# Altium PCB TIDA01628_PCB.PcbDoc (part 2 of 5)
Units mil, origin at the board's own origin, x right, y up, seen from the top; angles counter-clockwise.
Board outline 14212.6 x 5944.88 mil, 4 copper layers (Top Layer, GND, 5V, Bottom Layer), stack 60.8 mil thick; 304 components, 201 nets, 839 pads, 2143 vias.
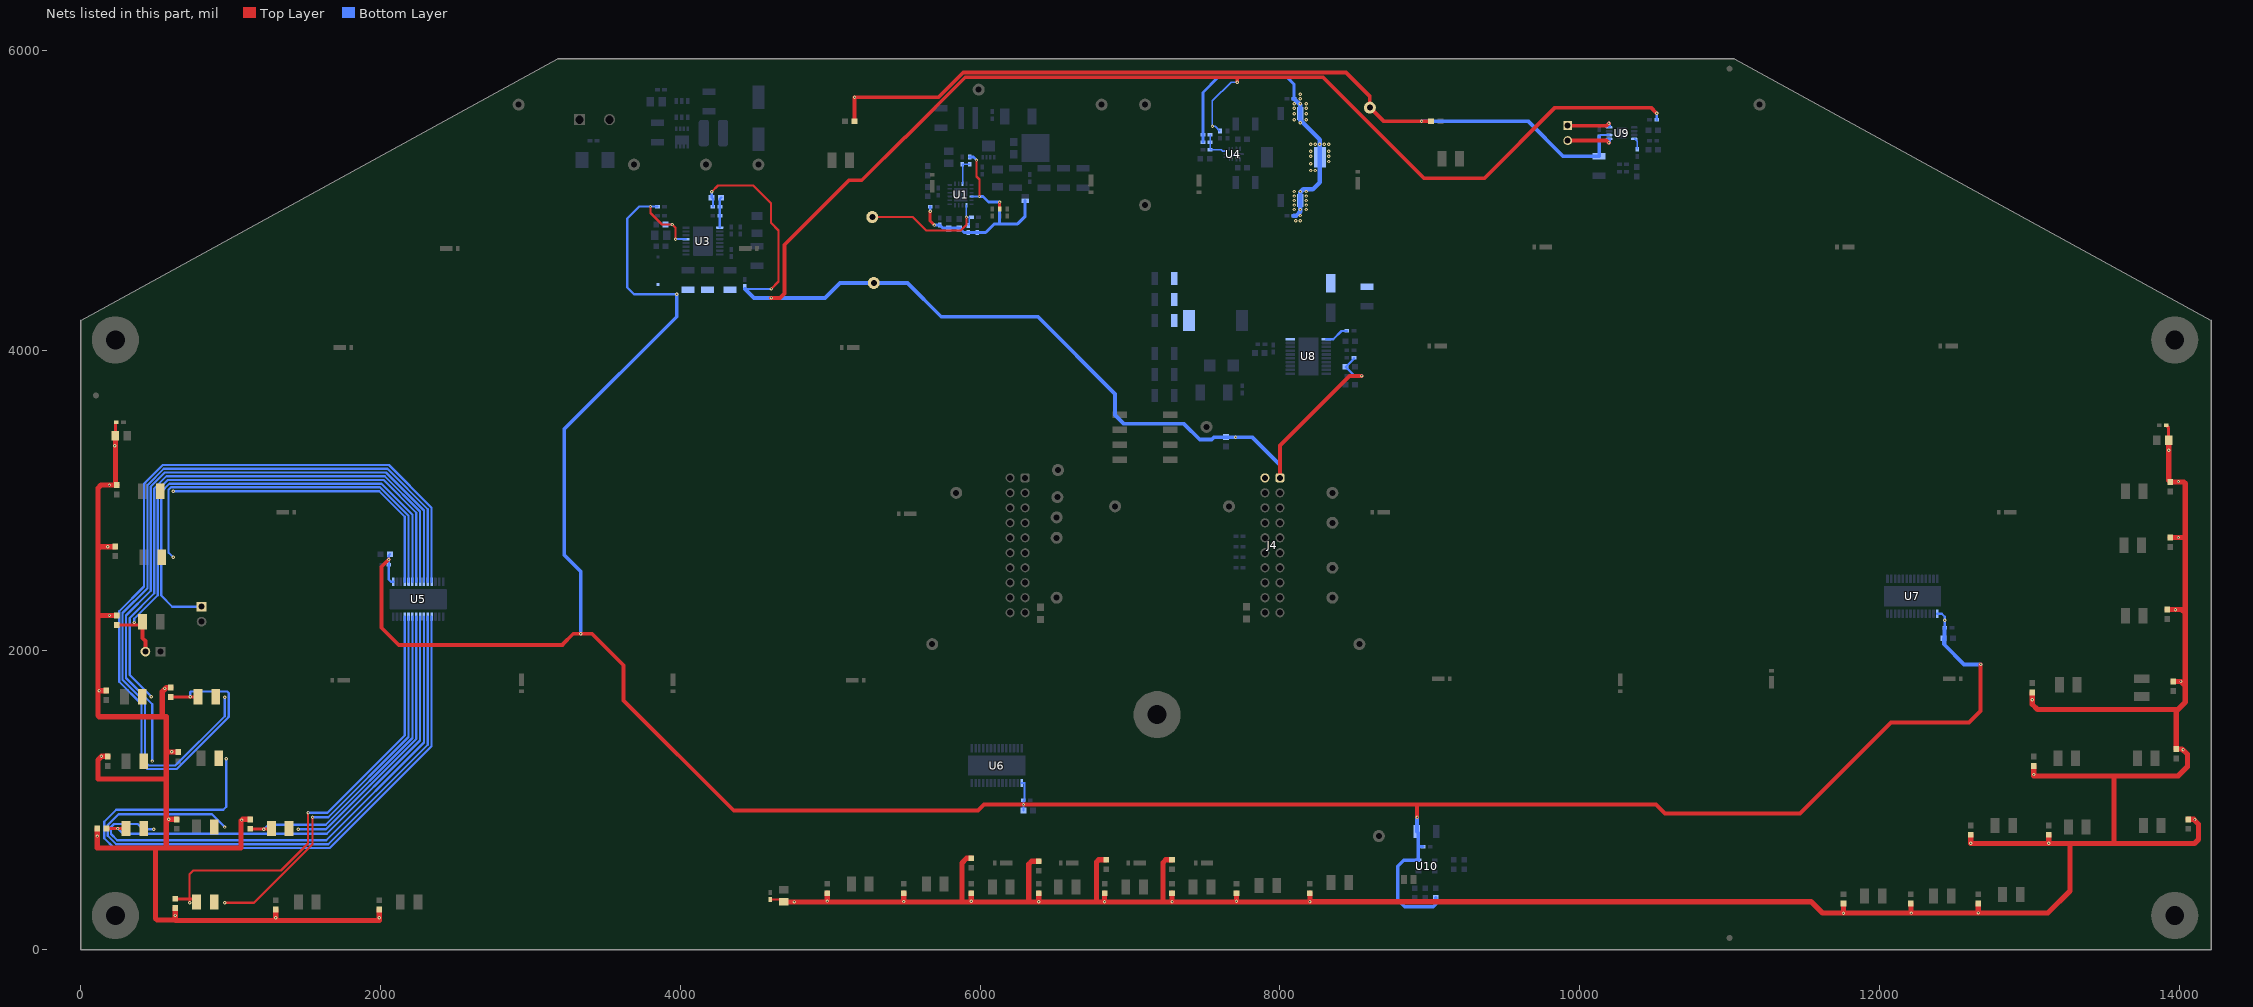
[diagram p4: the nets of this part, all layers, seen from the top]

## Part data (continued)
C16 C33 C43 C45 C47: library part CMP-0008019-2, "CAP, CERM, 4.7 uF, 16 V, +/- 10%, X7R, AEC-Q200 Grade 1, 0805", Cap_Case=0805, Manufacturer=MuRata, Supplier Part Number 1=GCM21BR71C475KA73K-ND, TempCo=X7R, Tolerance_%=10%, Value1=Unknown, Value2=16V, ValueDisplayed=4.7uF
C17 C34 C40 C49 C51 C53 C65 C66 C74: library part CMP-0007136-5, "CAP, CERM, 1 uF, 16 V, +/- 10%, X7R, AEC-Q200 Grade 1, 0603", Cap_Case=0603, Manufacturer=MuRata, Supplier Part Number 1=490-5241-6-ND, TempCo=X7R, Tolerance_%=10%, Value1=Unknown, Value2=16V, ValueDisplayed=1uF
C18: library part CMP-0006310-2, "CAP, CERM, 150 pF, 50 V, +/- 5%, C0G/NP0, AEC-Q200 Grade 1, 0402", Cap_Case=0402, Manufacturer=TDK, Supplier Part Number 1=445-5598-1-ND, TempCo=C0G/NP0, Tolerance_%=5%, Value1=Unknown, Value2=50V, ValueDisplayed=150pF
C19: library part CMP-0006321-2, "CAP, CERM, 4700 pF, 50 V, +/- 10%, X7R, AEC-Q200 Grade 1, 0402", Cap_Case=0402, Manufacturer=TDK, Supplier Part Number 1=445-5607-1-ND, TempCo=X7R, Tolerance_%=10%, Value1="0.413508 ohm", Value2=50V, ValueDisplayed=4700pF
C22 C27 C30 C32 C73: library part CMP-0007094-5, "CAP, CERM, 0.22 uF, 50 V, +/- 10%, X7R, AEC-Q200 Grade 1, 0603", Cap_Case=0603, Manufacturer=TDK, Supplier Part Number 1=445-6926-1-ND, TempCo=X7R, Tolerance_%=10%, Value1="0.021699 ohm", Value2=50V, ValueDisplayed=0.22uF
C23 C24 C25 C35 C36: library part CMP-0009154-2, "CAP, CERM, 22 uF, 16 V, +/- 20%, X7R, AEC-Q200 Grade 1, 1210", Cap_Case=1210_280, Manufacturer=TDK, Supplier Part Number 1=445-5723-1-ND, TempCo=X7R, Tolerance_%=20%, Value1="0.002582 ohm", Value2=16V, ValueDisplayed=22uF
C26 C39: library part CMP-0006324-2, "CAP, CERM, 0.01 uF, 50 V, +/- 10%, X7R, AEC-Q200 Grade 1, 0402", Cap_Case=0402, Manufacturer=TDK, Supplier Part Number 1=445-6893-1-ND, TempCo=X7R, Tolerance_%=10%, Value1="0.333065 ohm", Value2=50V, ValueDisplayed=0.01uF
C41: library part CMP-0006327-2, "CAP, CERM, 0.015 uF, 50 V, +/- 10%, X7R, AEC-Q200 Grade 1, 0402", Cap_Case=0402, Manufacturer=TDK, Supplier Part Number 1=445-6894-1-ND, TempCo=X7R, Tolerance_%=10%, Value1="0.2162 ohm", Value2=50V, ValueDisplayed=0.015uF
C61: library part CMP-0006791-4, "CAP, CERM, 4.7 pF, 50 V, +/- 5%, C0G/NP0, 0603", Cap_Case=0603, Manufacturer=AVX, Supplier Part Number 1=478-1159-1-ND, TempCo=C0G/NP0, Tolerance_%=5%, Value1="0.633 ohm", Value2=50V, ValueDisplayed=4.7pF
C63: library part CMP-0010728-1, "CAP, AL, 33 uF, 35 V, +/- 20%, 0.36 ohm, AEC-Q200 Grade 2, SMD", Cap_Case=D, Manufacturer=Panasonic, Supplier Part Number 1=PCE3840CT-ND, Tolerance_%=20%, Value1="0.36 ohm", Value2=35V, ValueDisplayed=33uF
C67: library part CMP-0006989-4, "CAP, CERM, 100 pF, 50 V, +/- 5%, C0G/NP0, 0603", Cap_Case=0603, Manufacturer=TDK, Supplier Part Number 1=445-173611-1-ND, TempCo=C0G/NP0, Tolerance_%=5%, Value1=Unknown, Value2=50V, ValueDisplayed=100pF
C70 C72: library part CMP-0007138-4, "CAP, CERM, 0.47 uF, 16 V, +/- 10%, X7R, AEC-Q200 Grade 1, 0603", Cap_Case=0603, Manufacturer=MuRata, Supplier Part Number 1=490-4775-1-ND, TempCo=X7R, Tolerance_%=10%, Value1=Unknown, Value2=16V, ValueDisplayed=0.47uF
C71: library part CMP-0006352-2, "CAP, CERM, 0.01 uF, 25 V, +/- 10%, X7R, 0402", Cap_Case=0402, Manufacturer=MuRata, Supplier Part Number 1=490-6043-2-ND, TempCo=X7R, Tolerance_%=10%, Value1=Unknown, Value2=25V, ValueDisplayed=0.01uF
D1: library part CMP-0028903-1, "Diode, Schottky, 60 V, 10 A, AEC-Q101, TO-277A", Manufacturer=Vishay-Semiconductor, Supplier Part Number 1=V10P6-M3/87A-ND, Value1=10A, Value2=0.59V
D2: library part CMP-0005564-2, "Diode, TVS, Bi, 33 V, SMB", Manufacturer="Diodes Inc.", Power_W=5W, Supplier Part Number 1=SMBJ33CA-FDICT-ND
D3 D4 D5 D6 D43 D44 D45 D46 D47 D48 D49 D50 D52 D53 D54 D55 D56 D57 D58 D59 D60 D61 D62 D63 D64 D65 D66 D67: "LED, White, SMD", Color=White, Manufacturer=OSRAM, Supplier Part Number 1="KW DPLS32.EC-6H6J-4F8G-1-ND", Value1=W, Value2=3.15V
D7 D8 D9 D25 D26 D27: library part CMP-0003010-2, "LED, Super Red, SMD", Color="Super Red", Manufacturer=OSRAM, Supplier Part Number 1=475-2516-1-ND, Value1=W, Value2=1.8V
D10 D11 D12 D13 D28 D29 D30 D31: library part CMP-0003012-2, "LED, Yellow, SMD", Color=Yellow, Manufacturer=OSRAM, Supplier Part Number 1=475-2562-1-ND, Value1=W, Value2=1.8V
D14: library part CMP-0003013-2, "LED, Blue, SMD", Color=Blue, Manufacturer=OSRAM, Supplier Part Number 1="LB T673-L2P1-25-Z-ND", Value1=W, Value2=3.1V
D15 D16 D17 D18 D19 D20 D21 D22 D23 D24 D32 D33 D34 D35 D36 D37 D38 D39 D40 D41 D42: library part CMP-0003009-2, "LED, Green, SMD", Color=Green, Manufacturer=OSRAM, Supplier Part Number 1="LG T67K-G2K1-24-Z-ND", Value1=W, Value2=1.8V
D51: library part CMP-0028810-1, "Diode, Schottky, 60 V, 3 A, AEC-Q101, SMA", Manufacturer="Fairchild Semiconductor", Supplier Part Number 1=SSA36CT-ND, Value1=3A, Value2=0.75V
D68 D69: "LED, Red, SMD", Color=red, Manufacturer=Lite-On, Supplier Part Number 1=160-1415-1-ND, Value1=W, Value2=2V
FID1 FID2 FID3: library part CMP-0077181-1, "Fiducial mark.  There is nothing to buy or mount.", Manufacturer=N/A
H1 H2 H3 H4 H5: library part CMP-0003617-1, "Machine Screw, Round, #4-40 x 1/4, Nylon, Philips panhead", Manufacturer="B&F Fastener Supply", Supplier Part Number 1=H542-ND
H6 H7 H8 H9 H10: library part CMP-0003610-1, "Standoff, Hex, 0.5\"L #4-40 Nylon", Manufacturer=Keystone, Supplier Part Number 1=36-1902C-ND
J1: library part CMP-0055551-1, "Header (Shrouded), 5.08mm, 2x1, Tin, R/A, TH", Color=Green, Current_A=12A, Manufacturer="Phoenix Contact", Supplier Part Number 1=277-1095-ND, Voltage_V=400V
J2 J3: library part CMP-0054566-1, "Header, 100mil, 2x1, Gold, TH", Color=Black, Current_A=3A, Manufacturer="Sullins Connector Solutions", Supplier Part Number 1=S1011E-02-ND, Voltage_V=1.8kV
J4 J5: library part CMP-0054623-1, "Header, 2.54mm, 10x2, Tin, TH", Color=Black, Current_A=3A, Manufacturer="Sullins Connector Solutions", Supplier Part Number 1=S2012E-10-ND
J6: library part CMP-0054947-1, "Header, 100mil, 2x1, Gold, TH", Manufacturer="TE Connectivity"
L1: library part CMP-0061081-1, "Inductor, Shielded, Composite, 560 nH, 11.3 A, 0.008 ohm, AEC-Q200 Grade 1, SMD", Manufacturer=Coilcraft, Value1="0.008 ohm", Value2=11.3A, ValueDisplayed=560nH
L2: library part CMP-0064228-1, "Inductor, Shielded Drum Core, Ferrite, 1 uH, 4 A, 0.049 ohm, SMD", Manufacturer="Wurth Elektronik", Supplier Part Number 1=732-1249-1-ND, Value1="0.049 ohm", Value2=4A, ValueDisplayed=1uH
L3: library part CMP-0063808-1, "Inductor, Shielded Drum Core, Ferrite, 1.8 uH, 2.45 A, 0.02 ohm, SMD", Manufacturer="Wurth Elektronik", Supplier Part Number 1=732-1094-1-ND, Value1="0.02 ohm", Value2=2.45A, ValueDisplayed=1.8uH
L4: library part CMP-0064214-1, "Inductor, Shielded Drum Core, Ferrite, 1.5 uH, 6.2 A, 0.0137 ohm, SMD", Manufacturer="Wurth Elektronik", Supplier Part Number 1=732-2972-1-ND, Value1="0.0137 ohm", Value2=6.2A, ValueDisplayed=1.5uH
L5: library part CMP-0064217-1, "Inductor, Shielded Drum Core, Ferrite, 4.7 uH, 4 A, 0.026 ohm, SMD", Manufacturer="Wurth Elektronik", Supplier Part Number 1=732-2975-1-ND, Value1="0.026 ohm", Value2=4A, ValueDisplayed=4.7uH
LBL1: library part CMP-0003625-1, "Thermal Transfer Printable Labels, 0.650\" W x 0.200\" H - 10,000 per roll", Manufacturer=Brady, Supplier Part Number 1=97C5133
Logo1: library part CMP-0074840-1, "ESD Susceptible Symbol"
Logo2: library part CMP-0074839-1
Logo3: library part CMP-0074847-1, "FCC_disclaimer"
NTG1: "Single point connection between nets."
Q1: library part CMP-0067553-1, "MOSFET, N-CH, 60 V, 15 A, AEC-Q101, 8-PowerVDFN", Alternate Manufacturer=None, Manufacturer="Diodes Inc.", Supplier Part Number 1=DMT6007LFG-13-ND, Value1="0.0085 ohm", Value2="41.3 nC"
Q2: library part CMP-0000806-1, "MOSFET, N-CH, 60 V, 12.8 A, AEC-Q101, 3.4x0.9x2.7mm", Alternate Manufacturer=None, Manufacturer="NXP Semiconductor", Supplier Part Number 1=568-13030-1-ND, Value2="4.4 nC"
Q3: library part CMP-0002104-2, "Ambient Light Sensor in 0805 Package", Manufacturer=Vishay-Semiconductor, Supplier Part Number 1=751-1056-1-ND
R1 R64: library part CMP-0016110-3, "RES, 2.0, 5%, 0.75 W, AEC-Q200 Grade 0, 2010", Manufacturer=Vishay-Dale, PartNumber=CRCW20102R00JNEF, Power_W=750mW, Supplier Part Number 1=541-2.0WCT-ND, TempCo="200 ppm/C", Tolerance_%=5%, Value2=0.75W, Value_Code=2R00, ValueDisplayed=2.0
R2 R5 R6 R8 R10 R15 R18 R67: library part CMP-0026822-3, "RES, 0, 5%, 0.063 W, AEC-Q200 Grade 0, 0402", Manufacturer=Vishay-Dale, Power_W=63mW, Supplier Part Number 1=541-0.0JCT-ND, TempCo="200 ppm/C", Tolerance_%=5%, Value2=0.063W, Value_Code=0000, ValueDisplayed=0
R3: library part CMP-0026404-2, "RES, 49.9, 1%, 0.063 W, AEC-Q200 Grade 0, 0402", Manufacturer=Vishay-Dale, Power_W=63mW, Supplier Part Number 1=541-49.9LCT-ND, TempCo="100 ppm/C", Tolerance_%=1%, Value2=0.063W, Value_Code=49R9, ValueDisplayed=49.9
R4: library part CMP-0018571-2, "RES, 0.015, 1%, 1 W, 1206", Manufacturer=Vishay-Dale, Power_W=1W, Supplier Part Number 1=WSLP-.015CT-ND, TempCo="75 ppm/C", Tolerance_%=1%, Value_Code=R015, ValueDisplayed=0.015
R7: library part CMP-0023011-2, "RES, 2.00, 1%, 0.1 W, 0603", Manufacturer="Yageo America", Power_W=100mW, Supplier Part Number 1=311-2.00HRCT-ND, TempCo="200 ppm/C", Tolerance_%=1%, Value2=0.1W, Value_Code=2R00, ValueDisplayed=2.00
R9: library part CMP-0025963-3, "RES, 10.0, 1%, 0.063 W, AEC-Q200 Grade 0, 0402", Manufacturer=Vishay-Dale, Power_W=63mW, Supplier Part Number 1=541-10.0LCT-ND, TempCo="100 ppm/C", Tolerance_%=1%, Value2=0.063W, Value_Code=10R0, ValueDisplayed=10.0
R11 R12: library part CMP-0022667-4, "RES, 9.53 k, 1%, 0.1 W, AEC-Q200 Grade 0, 0603", Manufacturer=Vishay-Dale, Power_W=100mW, Supplier Part Number 1=541-9.53KHCT-ND, TempCo="100 ppm/C", Tolerance_%=1%, Value2=0.1W, Value_Code=9k53, ValueDisplayed=9.53k
R13: library part CMP-0026405-2, "RES, 4.02 k, 1%, 0.063 W, AEC-Q200 Grade 0, 0402", Manufacturer=Vishay-Dale, Power_W=63mW, Supplier Part Number 1=541-4.02KLCT-ND, TempCo="100 ppm/C", Tolerance_%=1%, Value2=0.063W, Value_Code=4k02, ValueDisplayed=4.02k
R14: library part CMP-0018573-3, "RES, 0, 5%, 0.25 W, AEC-Q200 Grade 0, 1206", Manufacturer=Vishay-Dale, Power_W=250mW, Supplier Part Number 1=541-0.0ECT-ND, TempCo="200 ppm/C", Tolerance_%=5%, Value2=0.25W, Value_Code=0000, ValueDisplayed=0
R16 R20: library part CMP-0025950-3, "RES, 100 k, 1%, 0.063 W, AEC-Q200 Grade 0, 0402", Manufacturer=Vishay-Dale, Power_W=63mW, Supplier Part Number 1=541-100KLCT-ND, TempCo="100 ppm/C", Tolerance_%=1%, Value2=0.063W, Value_Code=100k
R17: library part CMP-0026058-3, "RES, 18.0 k, 1%, 0.063 W, AEC-Q200 Grade 0, 0402", Manufacturer=Vishay-Dale, Power_W=63mW, Supplier Part Number 1=541-18.0KLCT-ND, TempCo="100 ppm/C", Tolerance_%=1%, Value2=0.063W, Value_Code=18k0, ValueDisplayed=18.0k
R19: library part CMP-0026379-2, "RES, 43.2 k, 1%, 0.063 W, AEC-Q200 Grade 0, 0402", Manufacturer=Vishay-Dale, Power_W=63mW, Supplier Part Number 1=541-43.2KLCT-ND, TempCo="100 ppm/C", Tolerance_%=1%, Value2=0.063W, Value_Code=43k2, ValueDisplayed=43.2k
R21 R22: library part CMP-0025975-3, "RES, 11.0 k, 1%, 0.063 W, AEC-Q200 Grade 0, 0402", Manufacturer=Vishay-Dale, Power_W=63mW, Supplier Part Number 1=541-11.0KLCT-ND, TempCo="100 ppm/C", Tolerance_%=1%, Value2=0.063W, Value_Code=11k0, ValueDisplayed=11.0k
R23: library part CMP-0026196-2, "RES, 24.9 k, 1%, 0.063 W, AEC-Q200 Grade 0, 0402", Manufacturer=Vishay-Dale, Power_W=63mW, Supplier Part Number 1=541-24.9KLCT-ND, TempCo="100 ppm/C", Tolerance_%=1%, Value2=0.063W, Value_Code=24k9, ValueDisplayed=24.9k
R24 R25 R26 R27: library part CMP-0025843-4, "RES, 68, 5%, 0.1 W, AEC-Q200 Grade 0, 0603", Manufacturer=Vishay-Dale, Power_W=100mW, Supplier Part Number 1=541-68GCT-ND, TempCo="200 ppm/C", Tolerance_%=5%, Value2=0.1W, Value_Code=68R0, ValueDisplayed=68
R28 R29 R30 R31 R32 R33 R34 R35 R36 R37 R38 R39 R40 R41 R43 R44 R45 R46 R47 R48 R49 R50 R51 R52 R53 R54 R55 R56 R57 R58 R59 R60 R61 R62 R63: library part CMP-0022037-5, "RES, 130, 1%, 0.1 W, AEC-Q200 Grade 0, 0603", Manufacturer=Vishay-Dale, Power_W=100mW, Supplier Part Number 1=541-130HCT-ND, TempCo="100 ppm/C", Tolerance_%=1%, Value2=0.1W, Value_Code=130R, ValueDisplayed=130
R42: library part CMP-0025854-4, "RES, 75, 5%, 0.1 W, AEC-Q200 Grade 0, 0603", Manufacturer=Vishay-Dale, Power_W=100mW, Supplier Part Number 1=541-75GCT-ND, TempCo="200 ppm/C", Tolerance_%=5%, Value2=0.1W, Value_Code=75R0, ValueDisplayed=75
R65: library part CMP-0026504-2, "RES, 681 k, 1%, 0.063 W, AEC-Q200 Grade 0, 0402", Manufacturer=Vishay-Dale, Power_W=63mW, Supplier Part Number 1=541-681KLCT-ND, TempCo="100 ppm/C", Tolerance_%=1%, Value2=0.063W, Value_Code=681k
R66: library part CMP-0025997-3, "RES, 130 k, 1%, 0.063 W, AEC-Q200 Grade 0, 0402", Manufacturer=Vishay-Dale, Power_W=63mW, Supplier Part Number 1=541-130KLCT-ND, TempCo="100 ppm/C", Tolerance_%=1%, Value2=0.063W, Value_Code=130k
R68: library part CMP-0026883-3, "RES, 24 k, 5%, 0.063 W, AEC-Q200 Grade 0, 0402", Manufacturer=Vishay-Dale, Power_W=63mW, Supplier Part Number 1=541-24KJCT-ND, TempCo="200 ppm/C", Tolerance_%=5%, Value2=0.063W, Value_Code=24k0, ValueDisplayed=24k
R69: library part CMP-0022324-4, "RES, 30.1 k, 1%, 0.1 W, AEC-Q200 Grade 0, 0603", Manufacturer=Vishay-Dale, Power_W=100mW, Supplier Part Number 1=541-30.1KHCT-ND, TempCo="100 ppm/C", Tolerance_%=1%, Value2=0.1W, Value_Code=30k1, ValueDisplayed=30.1k
R70 R72 R79 R80 R81 R82: library part CMP-0026945-3, "RES, 51 k, 5%, 0.063 W, AEC-Q200 Grade 0, 0402", Manufacturer=Vishay-Dale, Power_W=63mW, Supplier Part Number 1=541-51KJCT-ND, TempCo="200 ppm/C", Tolerance_%=5%, Value2=0.063W, Value_Code=51k0, ValueDisplayed=51k
R71: library part CMP-0022125-4, "RES, 1.47 k, 1%, 0.1 W, AEC-Q200 Grade 0, 0603", Manufacturer=Vishay-Dale, Power_W=100mW, Supplier Part Number 1=541-1.47KHCT-ND, TempCo="100 ppm/C", Tolerance_%=1%, Value2=0.1W, Value_Code=1k47, ValueDisplayed=1.47k
R73 R75: library part CMP-0025992-3, "RES, 12.4 k, 1%, 0.063 W, AEC-Q200 Grade 0, 0402", Manufacturer=Vishay-Dale, Power_W=63mW, Supplier Part Number 1=541-12.4KLCT-ND, TempCo="100 ppm/C", Tolerance_%=1%, Value2=0.063W, Value_Code=12k4, ValueDisplayed=12.4k
R74: library part CMP-0026090-3, "RES, 1.58 k, 1%, 0.063 W, AEC-Q200 Grade 0, 0402", Manufacturer=Vishay-Dale, Power_W=63mW, Supplier Part Number 1=541-1.58KLCT-ND, TempCo="100 ppm/C", Tolerance_%=1%, Value2=0.063W, Value_Code=1k58, ValueDisplayed=1.58k
R76: library part CMP-0022679-3, "RES, 100, 1%, 0.1 W, AEC-Q200 Grade 0, 0603", Manufacturer=Panasonic, Power_W=100mW, Supplier Part Number 1=P100HCT-ND, TempCo="100 ppm/C", Tolerance_%=1%, Value2=0.1W, Value_Code=100R, ValueDisplayed=100
R77: library part CMP-0022560-4, "RES, 6.34 k, 1%, 0.1 W, AEC-Q200 Grade 0, 0603", Manufacturer=Vishay-Dale, Power_W=100mW, Supplier Part Number 1=541-6.34KHCT-ND, TempCo="100 ppm/C", Tolerance_%=1%, Value2=0.1W, Value_Code=6k34, ValueDisplayed=6.34k
R78: library part CMP-0022539-5, "RES, 634, 1%, 0.1 W, AEC-Q200 Grade 0, 0603", Manufacturer=Vishay-Dale, Power_W=100mW, Supplier Part Number 1=541-634HCT-ND, TempCo="100 ppm/C", Tolerance_%=1%, Value2=0.1W, Value_Code=634R, ValueDisplayed=634
S1: library part CMP-0002291-1, "Switch, SPST, Slide, Off-On, 4 Pos, 0.1A, 20V, SMD", CurrentRating_mA=100A, Manufacturer="CTS Electrocomponents", Supplier Part Number 1=CT2194MST-ND
SH-J1 SH-J2: library part CMP-0078738-1, "Single Operation 2.54mm Pitch Open Top Jumper Socket", Manufacturer=Harwin, Supplier Part Number 1=952-2881-ND
TP1 TP6 TP15 TP16 TP17 TP18 TP19 TP20 TP21 TP22 TP23 TP24 TP26 TP30: library part CMP-0055139-1, "Test Point, Miniature, White, TH", Color=White, Manufacturer=Keystone, Supplier Part Number 1=36-5002-ND
TP2 TP3 TP4 TP5 TP7 TP8 TP9 TP10 TP11 TP12 TP14 TP25 TP27 TP29: library part CMP-0055137-1, "Test Point, Miniature, Red, TH", Color=Red, Manufacturer=Keystone, Supplier Part Number 1=36-5000-ND
U1: library part CMP-0078203-1, "Wide VIN Automotive Low IQ Boost Controller, RUM0016C (WQFN-16)", Alternate Manufacturer="Texas Instruments", Alternate PartNumber=LM5150QRUMRQ1
U2: library part CMP-0079180-1, "Low Iq Always ON Smart Diode Controller, DBV0006A (SOT-23-6)", Alternate Manufacturer="Texas Instruments", Alternate PartNumber=LM74700QDBVRQ1
U3: library part CMP-0076311-2, "Automotive Qualified SIMPLE SWITCHER(R) 3.5V to 36V, 2A Synchronous Step-Down Voltage Converter, PWP0016G (TSSOP-16)", Alternate Manufacturer="Texas Instruments", Alternate PartNumber=LM43602QPWPTQ1
U4: library part CMP-0078599-1, "SIMPLE SWITCHER 3.8-V to 36-V 3-A Synchronous Step-Down Voltage Regulator, RNX0012A (VQFN-HR-12)", Alternate Manufacturer="Texas Instruments", Alternate PartNumber=LMR33630CQRNXTQ1
U5 U6 U7: library part CMP-0013686-4, "Power Logic 16-Bit Shift Register LED Driver with Diagnostic, PWP0028C (TSSOP-28)", Alternate Manufacturer="Texas Instruments"
U8: library part CMP-0073707-2, "Low-EMI, High-Performance 3-Channel LED Driver for Automotive Lighting, PWP0020D (TSSOP-20)", Alternate Manufacturer="Texas Instruments"
U9: library part CMP-0043047-1, "Automotive Catalog 3.1-W Mono, Fully Differential, Class-AB Audio Amplifier, -40 to 105 degC, 8-pin SOP (DGN8), Green (RoHS & no Sb/Br)", Manufacturer="Texas Instruments", Output Power(W)=2.45, Supply Max(Max)(Volt)=5.5, Supply Min(Min)(Volt)=2.5
U10: library part CMP-0077859-1, "Automotive Qualified Precision, Zero-Crossover, 20MHz, 0.9pA Ib, RRIO, CMOS Operational Amplifier, DBV0005A (SOT-23-5)", Alternate Manufacturer="Texas Instruments", Alternate PartNumber=OPA320AQDBVTQ1
ZZ1: library part CMP-0003616-3
ZZ2: library part CMP-0077236-1
ZZ3: library part CMP-0077237-1
ZZ4: library part CMP-0077238-1

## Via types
v1: diameter 22, hole 10, Top Layer to Bottom Layer, 1391 vias
v2: diameter 22, hole 10, Top Layer to Bottom Layer, tented both sides, 644 vias
v3: diameter 19.68, hole 7.87, Top Layer to Bottom Layer, tented both sides, 56 vias
v4: diameter 19.68, hole 7.87, Top Layer to Bottom Layer, 47 vias
v5: diameter 19.68, hole 7.87, Top Layer to Bottom Layer, tented top, 5 vias

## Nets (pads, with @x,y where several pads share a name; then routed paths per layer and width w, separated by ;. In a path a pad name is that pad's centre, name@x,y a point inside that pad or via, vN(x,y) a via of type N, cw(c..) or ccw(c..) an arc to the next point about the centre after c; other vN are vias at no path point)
3V3: C23.1 C24.1 C25.1 C26.1 C27.1 C34.1 C48.1 C49.1 C50.1 C51.1 C52.1 C53.1 C65.1 C75.1 C76.1 J4.1 L3.2 R16.2 R21.2 R22.2 R67.2 R70.1 R72.2 R76.2 R77.2 TP12.1 U3.5 U5.1 U6.1 U7.1 U10.5 | length 33329.6
  Top Layer w15: v2(3800,4960) 3800,4917 3877,4840 v2(3945,4840) 3967.2,4817.8 v2(3967.2,4742.8) ; v2(4208.5,5058.5) 4250,5100 4485,5100 4605,4980 4605,4850 4655,4800 4655,4460 v2(4605,4410)
  Top Layer w25: v2(2053.62,2605) 2005,2556.38 2005,2150 2120,2035 3213.6,2035 3213.6,2038.6 3285,2110 v2(3335,2110) 3410,2110 3620,1900 3620,1665 4355,930 5985,930 6025,970 v2(6288.5,970) 8915,970 ; v2(4605,4350) 4665,4350 4695,4380 4695,4705 5125,5135 5210,5135 5497.87,5422.87 5500.86,5422.87 5900.11,5822.13 7715,5822.13 ; v2(7715,5790) 7715,5822.13 ; J4.1@8000,3150 8000,3365 8465,3830 v2(8545,3830) ; v2(8915,885) 8915,970 ; v2(10513.62,5582.62) 10512.38,5582.62 10475,5620 9835,5620 9364.25,5149.25 8960.75,5149.25 8287.87,5822.13 7715,5822.13 ; v2(12675,1905) 12675,1595 12597.5,1517.5 12077.5,1517.5 11470,910 10570,910 10510,970 8915,970
  Bottom Layer w10: R21.2@7600,5463.62 7568.62,5495 v2(7550,5495) 7550,5665 7675,5790 v2(7715,5790)
  Bottom Layer w15: C49.1@2061.5,2640 2053.62,2632.13 v2(2053.62,2605) C48.1@2053.62,2570 2053.62,2471.38 2068.86,2456.14 U5.1@2083.66,2456.14 ; R22.2@3846.38,4960 v2(3800,4960) 3725,4960 3645,4880 3645,4420 3690,4375 v2(3975,4375) ; C34.1@3901.5,4840 v2(3945,4840) ; v2(3967.2,4742.8) U3.5@4037.79,4742.8 ; v2(4208.5,5058.5) C27.1@4208.5,5020 4216.38,5012.13 R16.2@4216.38,4960 ; 4430,4410 v2(4605,4410) ; U6.1@6276.34,1113.86 6296.14,1113.86 6296.38,1113.62 6296.38,1000 6288.5,992.13 v2(6288.5,970) C53.1@6288.5,930 ; R67.2@8493.62,3950 8493.62,3945.12 C65.1@8438.5,3890 8493.62,3834.88 R70.1@8493.62,3830 v2(8545,3830) ; 8922.73,689 8923.73,690 ; R72.2@10513.62,5540 v2(10513.62,5582.62) ; U7.1@12386.34,2243.86 12416.14,2243.86 12436.38,2223.62 v2(12436.38,2200) C50.1@12436.38,2150 12428.5,2142.13 C51.1@12428.5,2080
  Bottom Layer w20: 8923.73,690 C76.1@8955.08,690
  Bottom Layer w23: C75.1@8922.73,781.01 8922.73,689 U10.5@8922.73,597.4 ; U10.5@8924.57,597.4 U10.5@8922.73,597.4 ; R77.2@9038.7,348.5 9038.7,304.7 9023,289 8832,289 8787,334 8787,557 8827.4,597.4 U10.5@8922.73,597.4
  Bottom Layer w25: v2(3335,2110) 3335,2525 3225,2635 3225,3475 3975,4225 v2(3975,4375) ; 4430,4410 4490,4350 4965,4350 5065,4450 TP12.1@5290,4450 5515,4450 5740,4225 6385,4225 6900,3710 6900,3570 6960,3510 7360,3510 7465,3405 7545,3405 7561.5,3421.5 R76.2@7640,3421.5 v2(7703.5,3421.5) 7813.5,3421.5 8000,3235 J4.1@8000,3150 ; C75.1@8913.74,790 8913.74,883.74 v2(8915,885) ; C51.1@12428.5,2080 12428.5,2041.5 12436.38,2033.62 ; C50.1@12436.38,2150 12436.38,2033.62 ; v2(12675,1905) 12565,1905 12436.38,2033.62
5V: C35.1 C36.1 C37.1 C38.1 C39.1 C42.1 C43.1 C44.1 C45.1 C46.1 C47.1 C55.1 C56.1 C57.1 C62.1 C63.1 C64.1 C68.1 C69.1 J4.2 L4.2 L5.1 R20.2 R24.2 R25.2 R26.2 R27.2 R28.2 R29.2 R30.2 R31.2 R32.2 R33.2 R34.2 R35.2 R36.2 R37.2 R38.2 R39.2 R40.2 R41.2 R42.2 R43.2 R44.2 R45.2 R46.2 R47.2 R48.2 R49.2 R50.2 R51.2 R52.2 R53.2 R54.2 R55.2 R56.2 R57.2 R58.2 R59.2 R60.2 R61.2 R62.2 R63.2 TP14.1 U8.1 U8.20 U9.6 | length 34613.3
  Top Layer w15: C44.1@4600,336.38 4673.62,336.38 C45.1@4690,320
  Top Layer w20: C43.1@230,3430 230,3513.62 C42.1@236.38,3520 ; C46.1@13913.62,3500 13930,3483.62 C47.1@13930,3400
  Top Layer w25: R60.2@5161.5,5530 v2(5161.5,5688.5) 5720,5688.5 5886.5,5855 8440,5855 8600,5695 TP14.1@8600,5620 8690,5530 v2(8945,5530) R59.2@9008.5,5530
  Top Layer w35: R30.2@108.5,810 108.5,680.5 498,680.5 ; R44.2@170,1731.5 168.5,1730 v2(121,1730) 113,1722 ; R45.2@180,1291.5 v2(136.5,1291.5) 113,1268 113,1140 569,1140 ; R34.2@230,2691.5 228.5,2690 129,2690 113,2674 ; C43.1@230,3430 230,3111.5 R43.2@240,3101.5 134.5,3101.5 113,3080 113,2674 ; R28.2@240,2231.5 114.5,2231.5 113,2230 ; 543,1558 543,1724.27 570.23,1751.5 R29.2@600,1751.5 ; R32.2@630,278.5 630,199 ; R36.2@640,871.5 v2(586.5,871.5) 569,854 ; R35.2@650,1321.5 v2(605.5,1321.5) 573.32,1321.5 569,1317.17 ; R31.2@1130,871.5 1077.5,871.5 1067.5,861.5 1067.5,680.5 569,680.5 ; R62.2@1300,268.5 1300,201 1296,197 ; R63.2@1990,268.5 1990,197 1296,197 ; C45.1@4690,320 v2@4986,320 ; R42.2@4980,378.5 v2(4980,326) v2@4986,320 ; R37.2@5490,378.5 v2(5490,323) v2@5487,320 ; R46.2@5940,378.5 v2(5940,324) v2@5944,320 ; R24.2@5940,611.5 5909.5,611.5 5878,580 5878,320 ; R47.2@6390,378.5 v2(6390,322) v2@6388,320 ; R25.2@6390,591.5 6343.5,591.5 6324,572 6324,320 ; R48.2@6830,378.5 v2(6830,322) v2@6828,320 ; R26.2@6840,601.5 6791.5,601.5 6776,586 6776,320 ; R49.2@7280,378.5 v2(7280,321) v2@7279,320 ; R27.2@7280,601.5 7238.5,601.5 7219,582 7219,320 ; R50.2@7710,378.5 v2(7710,325) v2@7705,320 ; R33.2@8200,378.5 v2(8200,322) ; R51.2@11760,308.5 11760,253 v2@11753,246 ; R52.2@12210,308.5 12210,248 v2(12212,246) ; R53.2@12610,768.5 v2(12610,711) v2(13130,711) ; R38.2@12660,308.5 v2(12660,247) v2@12659,246 ; R56.2@13020,1718.5 13020,1639 13054,1605 13992,1605 ; R55.2@13030,1228.5 13030,1161 13565,1161 ; R54.2@13130,768.5 v2(13130,711) ; R58.2@13920,2271.5 14016.5,2271.5 14041,2247 ; C47.1@13930,3400 13930,3131.5 R41.2@13940,3121.5 13941.5,3123 14030,3123 14041,3112 14041,2758 ; R61.2@13940,2751.5 14034.5,2751.5 14041,2758 ; R57.2@13960,1791.5 v2(14011.5,1791.5) 14041,1762 ; R39.2@14060,871.5 14096.5,871.5 14129,839 14129,737 14103,711 13567,711 ; 113,1722 113,2230 ; 113,1722 113,1564 121,1556 569,1556 569,1317.17 ; 113,2230 113,2674 ; 498,680.5 498,210 509,199 630,199 ; 498,680.5 569,680.5 ; 569,680.5 569,854 ; 569,854 569,1140 ; 569,1140 569,1317.17 ; 630,199 632,197 1296,197 ; v2@4986,320 v2@5487,320 ; v2@5487,320 5878,320 ; 5878,320 v2@5944,320 ; v2@5944,320 6324,320 ; 6324,320 v2@6388,320 ; v2@6388,320 6776,320 ; 6776,320 v2@6828,320 ; v2@6828,320 7219,320 ; 7219,320 v2@7279,320 ; v2@7279,320 v2@7705,320 ; v2@7705,320 8198,320 v2(8200,322) ; v2(8200,322) 11544,322 11620,246 v2@11753,246 ; v2@11753,246 v2(12212,246) ; v2(12212,246) v2@12659,246 ; v2@12659,246 13123,246 13271,394 13271,711 ; v2(13130,711) 13271,711 ; 13271,711 13567,711 ; 13565,1161 13565,713 13567,711 ; 13565,1161 13993,1161 14055,1223 14055,1306 14019.5,1341.5 R40.2@13980,1341.5 13980,1593 13992,1605 ; 13992,1605 14041,1654 14041,1762 ; 14041,1762 14041,2247 ; 14041,2247 14041,2758
  Bottom Layer w15: 8355.16,4075.16 8410,4130 C62.1@8446.38,4130 ; C69.1@10130,5426.38 10140.83,5437.2 U9.6@10196.34,5437.2
  Bottom Layer w17: U8.1@8310.08,4075.16 8355.16,4075.16
  Bottom Layer w20: R20.2@7486.38,5390 C39.1@7486.38,5440 7486.38,5721.38 7587.13,5822.13 8047.87,5822.13 8093.62,5776.38 C37.1@8093.62,5680
  Bottom Layer w25: v2(8945,5530) 9655,5530 9890.04,5294.96 C68.1@10130,5294.96 C69.1@10130,5426.38
  Bottom Layer w30: C38.1@8093.62,4900 8110,4900 8134.96,4924.96 C35.1@8134.96,5000 8134.96,5054.96 8155,5075 8220,5075 8267.17,5122.17 L4.2@8267.17,5290 8267.17,5405.14 8134.96,5537.35 C36.1@8134.96,5580 8134.96,5638.66 C37.1@8093.62,5680
  other v2: 1300,215 1990,215 630,230 11760,245 4760,320 108.5,760 1072.5,866.5 14105,870 13030,1170 14026,1335 13020,1670 560,1745 190,2231.5 13975,2270 178.75,2690 13995,2751.5 190,3101.5 13995,3125 13930,3335 225,3365 8105,4865 8135,4865 8135,4900 8095,4940 8135,4940 8175,4940 8095,4970 8175,4970 8095,5000 8175,5000 8095,5030 8175,5030 8095,5060 8135,5060 8175,5060 8205,5200 8235,5200 8205,5245 8325,5260 8205,5295 8325,5295 8205,5330 8325,5330 8205,5375 8235,5375 8265,5375 8295,5375 8325,5375 8135,5520 8095,5540 8175,5540 8095,5580 8175,5580 8095,5615 8175,5615 8095,5645 8135,5645 8175,5645 8135,5680 8135,5710
AGND: C13.2 C14.2 C15.2 C18.2 C19.2 NTG1.1 R10.1 R11.1 R12.1 U1.11 | length 1662.8
  Top Layer w15: v2(5975,5270) 5975,5160 5995,5140 v2@5995,5030
  Top Layer w20: v2(5666.38,4928.25) 5666.38,4863.62 v2(5693.62,4836.38) ; C14.2@6130,4943.62 v2(6130,4990)
  Bottom Layer w10: U1.11@5941.85,5027.2 5992.2,5027.2 v2@5995,5030
  Bottom Layer w15: v2(5666.38,4928.25) R10.1@5666.38,4960 ; U1.11@5941.85,5027.2 5992.2,5027.2 v2(5995,5027.2)
  Bottom Layer w20: v2(5693.62,4836.38) C13.2@5730,4836.38 5747.87,4818.5 5860,4818.5 5892.13,4786.38 C18.2@5920,4786.38 C19.2@5980,4786.38 6036.38,4786.38 6095,4845 6250,4845 6300,4895 NTG1.1@6300,5000 ; C15.2@5930,5290 5955,5290 v2(5975,5270) ; v2(5995,5027.2) 5995.61,5026.59 6018.41,5026.59 6055,4990 v2(6130,4990) 6130,4845
Audio_In: R73.1 U9.4 | length 79.5
  Bottom Layer w10: U9.4@10363.66,5411.61 10366.4,5411.61 10383.23,5394.79 R73.1@10383.23,5341.78
Audio_out+: J6.2 U9.5 | length 310
  Top Layer w25: J6.2@9920,5400 10180,5400 v2(10195,5385)
  Bottom Layer w13: J6.2@9920,5400 J6.2@9923.74,5396.26
  Bottom Layer w25: v2(10195,5385) 10195,5406.63 U9.5@10196.34,5407.97
Audio_out-: J6.1 U9.8 | length 308.8
  Top Layer w25: J6.1@9920,5500 10180,5500 v2(10195,5515)
  Bottom Layer w13: J6.1@9920,5500 J6.1@9925,5505
  Bottom Layer w25: v2(10195,5515) 10196.34,5513.66 U9.8@10196.34,5495
AVCC: C15.1 R9.1 U1.7 | length 182.1
  Bottom Layer w10: U1.7@5882.8,5111.85 5882.8,5239.96 R9.1@5880,5242.76 C15.1@5930,5242.76
COMP: C18.1 R13.2 TP6.1 U1.13 | length 888.3
  Top Layer w15: TP6.1@5280,4890 5550,4890 5640,4800 5870,4800 5908.39,4838.39 v2(5908.39,4890)
  Bottom Layer w10: U1.13@5908.39,4968.15 v2(5908.39,4890) 5926.38,4890 5926.38,4840 C18.1@5920,4833.62
D0: D32.2 U5.4 | length 2049.5
  Bottom Layer w15: v2(615,3060) 1990,3060 2160.43,2889.57 U5.4@2160.43,2456.14
D1: D10.2 U5.5 | length 2596.2
  Bottom Layer w15: 590,3075 585,3070 ; v2(615,2620) 585,2650 585,3070 ; U5.5@2186.02,2456.14 2186.02,2896.33 1995.97,3086.37 601.37,3086.37 585,3070
D2: J3.1 U5.6 | length 3223.4
  Bottom Layer w15: J3.1@805.09,2290 610,2290 535,2365 535,3055 590,3110 2005,3110 2211.61,2903.39 U5.6@2211.61,2456.14
D3: D7.1 J2.2 R28.1 U5.7 | length 3639.8
  Top Layer w20: R28.1@240,2168.5 389.45,2168.5 D7.1@410.94,2190
  Top Layer w25: D7.1@410.94,2190 410.94,2080.06 430,2061 J2.2@430,1990
  Bottom Layer w15: v2(355,2185) 355,2210 512.13,2367.13 512.13,3067.13 580,3135 2020,3135 2237.2,2917.8 U5.7@2237.2,2456.14
D4: D15.2 U5.8 | length 3890.5
  Bottom Layer w15: v2(470,1690) 325,1835 325,2215 489.25,2379.25 489.25,3079.25 570,3160 2027.65,3160 2262.8,2924.86 U5.8@2262.8,2456.14
D5: D33.2 U5.9 | length 4413.4
  Bottom Layer w15: v2(475,1260) 475,1640 300.75,1814.25 300.75,2230.75 466.38,2396.38 466.38,3091.38 560,3185 2035,3185 2288.39,2931.61 U5.9@2288.39,2456.14
D6: D25.2 U5.10 | length 5293.5
  Bottom Layer w15: v2(960,1685) 960,1560 630,1230 451.93,1230 426.93,1255 426.93,1653.07 277.87,1802.13 277.87,2247.87 443.5,2413.5 443.5,3101.16 552.35,3210 2045,3210 2313.98,2941.02 U5.10@2313.98,2456.14
D7: D25.1 R29.1 U5.11 | length 5981.6
  Top Layer w20: R29.1@600,1688.5 v2(730,1688.5) 779.45,1688.5 D25.1@780.94,1690
  Bottom Layer w15: 255,1815 255,1790 ; v2(730,1688.5) 730,1720 735,1725 976.37,1725 986.37,1715 986.37,1556.37 982.87,1552.87 982.87,1550.53 639.47,1207.13 442.45,1207.13 404.06,1245.53 404.06,1640.94 255,1790 ; U5.11@2339.57,2456.14 2339.57,2950.43 2055,3235 545,3235 420.63,3110.63 420.63,2425.63 255,2260 255,1790
D8: D28.2 U5.18 | length 4643.8
  Bottom Layer w15: v2(970,1275) 970,955 950,935 234.78,935 155,855.22 155,745 220,680 1660,680 2339.57,1359.57 U5.18@2339.57,2223.86
D9: D11.2 U5.19 | length 4207.4
  Bottom Layer w15: v2(960,820) 875,905 250,905 178.15,833.15 178.15,761.85 235,705 1650,705 2313.98,1368.98 U5.19@2313.98,2223.86
D10: D8.2 U5.20 | length 3568.3
  Bottom Layer w15: v2(485,805) 414.06,805 379.06,840 220,840 201.02,821.02 201.02,773.98 242.87,732.13 1637.13,732.13 2288.39,1383.39 U5.20@2288.39,2223.86
D11: D8.1 R30.1 U5.21 | length 3245.8
  Top Layer w20: R30.1@171.5,810 v2(245,810) D8.1@300.94,810
  Bottom Layer w15: v2(245,810) 280,775 1640,775 2262.8,1397.8 U5.21@2262.8,2223.86
D12: D26.2 U5.22 | length 1853.3
  Bottom Layer w15: v2(1450,805) 1635,805 2237.2,1407.2 U5.22@2237.2,2223.86
D13: D26.1 R31.1 U5.23 | length 2195.3
  Top Layer w20: R31.1@1130,808.5 1269.45,808.5 D26.1@1270.94,810
  Bottom Layer w15: v2(1220,805) 1250,835 1632.65,835 2211.61,1413.96 U5.23@2211.61,2223.86
D14: D9.2 U5.24 | length 2592.6
  Top Layer w15: v2(960,315) 1155,315 1545,705 v2(1545,885)
  Bottom Layer w15: v2(1545,885) 1650.3,885 2186.02,1420.72 U5.24@2186.02,2223.86
D15: D9.1 R32.1 U5.25 | length 3114.5
  Top Layer w15: v2(725,315) 725,341.5 725,505 750,530 1335,530 ; 1365,560 1335,530 ; v2(1515,915) 1515,710 1335,530
  Top Layer w20: R32.1@630,341.5 725,341.5 749.45,341.5 D9.1@770.94,320
  Bottom Layer w15: v2(1515,915) 1645,915 2160.43,1430.43 U5.25@2160.43,2223.86
FB_3V3: C27.2 R16.1 R19.2 U3.9 | length 204.3
  Bottom Layer w15: U3.9@4262.2,4819.57 4262.2,5010.71 C27.2@4271.5,5020
FB_5V: C39.2 R20.1 R23.2 U4.7 | length 205.5
  Bottom Layer w9: C39.2@7533.62,5440 R23.2@7533.62,5340 7608.06,5340 7618.37,5329.69 U4.7@7634.88,5329.69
